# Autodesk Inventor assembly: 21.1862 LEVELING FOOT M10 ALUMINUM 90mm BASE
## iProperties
Created: 2007-03
Part Number: 21.1862 LEVELING FOOT M10 ALUMINUM 90mm BASE
Document SubType Name: Assembly
Designer: Andy Moles
Author: Andy Moles
